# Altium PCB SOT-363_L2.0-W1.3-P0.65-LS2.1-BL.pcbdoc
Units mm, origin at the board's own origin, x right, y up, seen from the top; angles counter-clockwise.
Board outline 15.2 x 15.53 mm, 2 copper layers (Top Layer, Bottom Layer), stack 0.07 mm thick; 1 components, 0 nets, 6 pads, 0 vias.
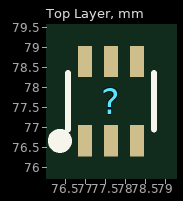
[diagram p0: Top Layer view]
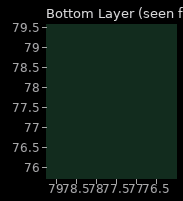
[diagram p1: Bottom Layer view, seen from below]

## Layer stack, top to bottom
Top Solder Mask Layer: solder mask 0.01, Dk 3.3
Top Layer: signal copper 0.035
Bottom Layer: signal copper 0.035
Bottom Solder Mask Layer: solder mask 0.01, Dk 3.3

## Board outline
85.054,69.85 69.85,69.85 69.85,85.38 85.054,85.38

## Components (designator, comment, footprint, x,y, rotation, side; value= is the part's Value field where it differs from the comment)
? "SOT-363_L2.0-W1.3-P0.65-LS2.1-BL" SOT-363_L2.0-W1.3-P0.65-LS2.1-BL 77.627,77.65 r0 top

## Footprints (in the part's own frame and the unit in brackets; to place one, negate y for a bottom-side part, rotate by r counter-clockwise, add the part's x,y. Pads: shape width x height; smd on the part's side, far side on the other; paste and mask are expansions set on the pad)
SOT-363_L2.0-W1.3-P0.65-LS2.1-BL [mm]
  rect 0.35x0.78 smd paste+0 mask+0.051: 1(-0.65,-0.99) 2(0,-0.99) 3(0.65,-0.99) 4(0.65,0.99) 5(0,0.99) 6(-0.65,0.99)
  silkscreen extent -1.43,-1.14 1.08,0.7

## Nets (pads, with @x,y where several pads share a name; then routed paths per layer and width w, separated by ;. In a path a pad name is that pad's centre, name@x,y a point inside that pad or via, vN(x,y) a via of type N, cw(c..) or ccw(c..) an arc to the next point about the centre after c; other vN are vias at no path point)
pads on no net: ?.1 ?.2 ?.3 ?.4 ?.5 ?.6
